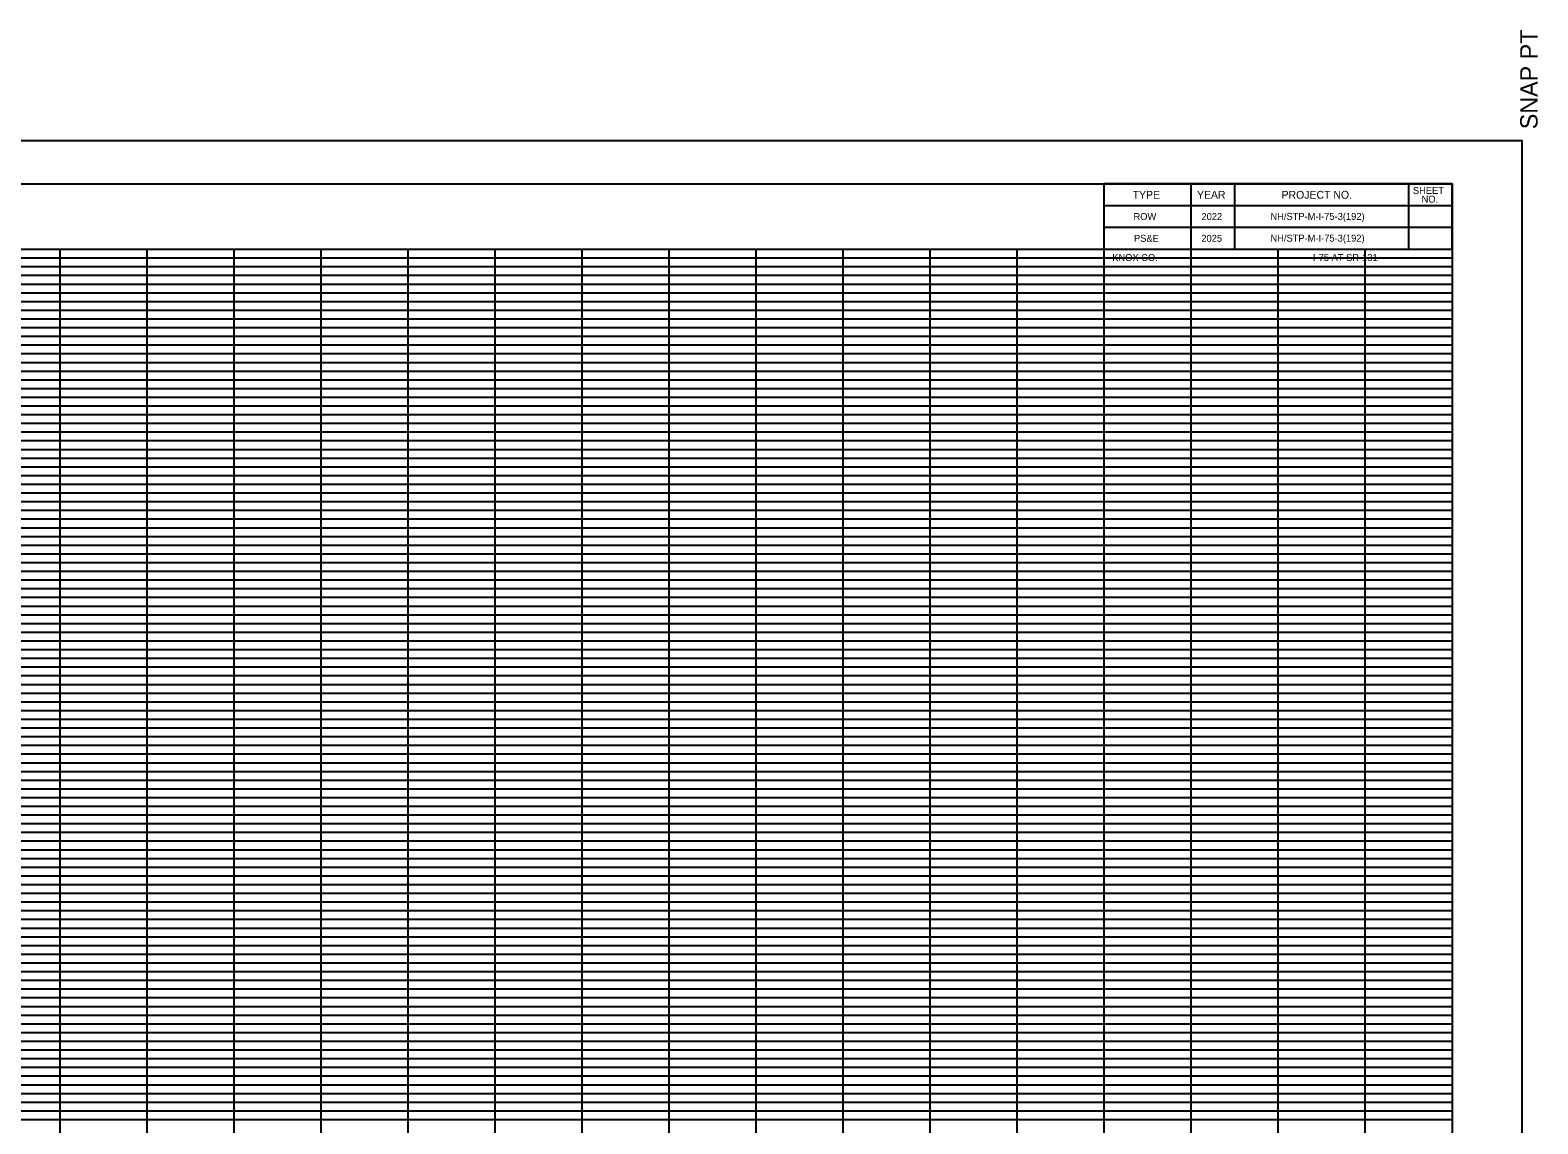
# Model space of a CAD drawing. Extents: x -1.4 to 33, y -2.5 to 22.5.
import ezdxf

# ---------------------------------------------------------------- set-up
doc = ezdxf.new("R2010")
doc.units = 0
for name, color, linetype in [('DESIGN - SCRATCH - User 1', 7, 'Continuous'), ('DESIGN - SHEET - Corner Text', 7, 'Continuous'), ('DESIGN - SHEET - Light Grid', 7, 'Continuous'), ('DESIGN - SHEET - Linework', 7, 'Continuous'), ('DESIGN - SHEET - Plot Shape', 7, 'Continuous')]:
    doc.layers.add(name, color=color, linetype=linetype)

msp = doc.modelspace()

# ---------------------------------------------------------------- linework, layer by layer
at = {"layer": 'DESIGN - SCRATCH - User 1'}
for p, q in [((28.5, 20.375), (28.5, 20.375)), ((29.25, 20.375), (29.25, 20.375)), ((30.5, 20.375), (30.5, 20.375)), ((31.75, 20.375), (31.75, 20.375)), ((28.5, 20.125), (28.5, 20.125)), ((29.25, 20.125), (29.25, 20.125)), ((30.5, 20.125), (30.5, 20.125)), ((31.75, 20.125), (31.75, 20.125))]:
    msp.add_line(p, q, dxfattribs=at)
at = {"layer": 'DESIGN - SHEET - Light Grid'}
for p, q in [((0, 19.9), (32, 19.9)), ((0, 19.8), (32, 19.8)), ((0, 19.7), (32, 19.7)), ((0, 19.6), (32, 19.6)), ((0, 19.5), (32, 19.5)), ((0, 19.4), (32, 19.4)), ((0, 19.3), (32, 19.3)), ((0, 19.2), (32, 19.2)), ((0, 19.1), (32, 19.1)), ((0, 18.9), (32, 18.9)), ((0, 18.8), (32, 18.8)), ((0, 18.7), (32, 18.7)), ((0, 18.6), (32, 18.6)), ((0, 18.5), (32, 18.5)), ((0, 18.4), (32, 18.4)), ((0, 18.3), (32, 18.3)), ((0, 18.2), (32, 18.2)), ((0, 18.1), (32, 18.1)), ((0, 17.9), (32, 17.9)), ((0, 17.8), (32, 17.8)), ((0, 17.7), (32, 17.7)), ((0, 17.6), (32, 17.6)), ((0, 17.5), (32, 17.5)), ((0, 17.4), (32, 17.4)), ((0, 17.3), (32, 17.3)), ((0, 17.2), (32, 17.2)), ((0, 17.1), (32, 17.1)), ((0, 16.9), (32, 16.9)), ((0, 16.8), (32, 16.8)), ((0, 16.7), (32, 16.7)), ((0, 16.6), (32, 16.6)), ((0, 16.5), (32, 16.5)), ((0, 16.4), (32, 16.4)), ((0, 16.3), (32, 16.3)), ((0, 16.2), (32, 16.2)), ((0, 16.1), (32, 16.1)), ((0, 15.9), (32, 15.9)), ((0, 15.8), (32, 15.8)), ((0, 15.7), (32, 15.7)), ((0, 15.6), (32, 15.6)), ((0, 15.5), (32, 15.5)), ((0, 15.4), (32, 15.4)), ((0, 15.3), (32, 15.3)), ((0, 15.2), (32, 15.2)), ((0, 15.1), (32, 15.1)), ((0, 14.9), (32, 14.9)), ((0, 14.8), (32, 14.8)), ((0, 14.7), (32, 14.7)), ((0, 14.6), (32, 14.6)), ((0, 14.5), (32, 14.5)), ((0, 14.4), (32, 14.4)), ((0, 14.3), (32, 14.3)), ((0, 14.2), (32, 14.2)), ((0, 14.1), (32, 14.1)), ((0, 13.9), (32, 13.9)), ((0, 13.8), (32, 13.8)), ((0, 13.7), (32, 13.7)), ((0, 13.6), (32, 13.6)), ((0, 13.5), (32, 13.5)), ((0, 13.4), (32, 13.4)), ((0, 13.3), (32, 13.3)), ((0, 13.2), (32, 13.2)), ((0, 13.1), (32, 13.1)), ((0, 12.9), (32, 12.9)), ((0, 12.8), (32, 12.8)), ((0, 12.7), (32, 12.7)), ((0, 12.6), (32, 12.6)), ((0, 12.5), (32, 12.5)), ((0, 12.4), (32, 12.4)), ((0, 12.3), (32, 12.3)), ((0, 12.2), (32, 12.2)), ((0, 12.1), (32, 12.1)), ((0, 11.9), (32, 11.9)), ((0, 11.8), (32, 11.8)), ((0, 11.7), (32, 11.7)), ((0, 11.6), (32, 11.6)), ((0, 11.5), (32, 11.5)), ((0, 11.4), (32, 11.4)), ((0, 11.3), (32, 11.3)), ((0, 11.2), (32, 11.2)), ((0, 11.1), (32, 11.1)), ((0, 10.9), (32, 10.9)), ((0, 10.8), (32, 10.8)), ((0, 10.7), (32, 10.7)), ((0, 10.6), (32, 10.6)), ((0, 10.5), (32, 10.5)), ((0, 10.4), (32, 10.4)), ((0, 10.3), (32, 10.3)), ((0, 10.2), (32, 10.2)), ((0, 10.1), (32, 10.1))]:
    msp.add_line(p, q, dxfattribs=at)
at = {"layer": 'DESIGN - SHEET - Linework'}
for p, q in [((32, 20.75), (28, 20.75)), ((28, 20), (28, 20.75)), ((29, 20), (29, 20.75)), ((29.5, 20), (29.5, 20.75)), ((31.5, 20), (31.5, 20.75)), ((32, 20), (32, 20.75)), ((32, 20.5), (28, 20.5)), ((32, 20.25), (28, 20.25)), ((0, 20), (32, 20)), ((16, 0), (16, 20)), ((17, 0), (17, 20)), ((18, 0), (18, 20)), ((19, 0), (19, 20)), ((20, 0), (20, 20)), ((21, 0), (21, 20)), ((22, 0), (22, 20)), ((23, 0), (23, 20)), ((24, 0), (24, 20)), ((25, 0), (25, 20)), ((26, 0), (26, 20)), ((27, 0), (27, 20)), ((28, 0), (28, 20)), ((29, 0), (29, 20)), ((30, 0), (30, 20)), ((31, 0), (31, 20)), ((0, 19), (32, 19)), ((0, 18), (32, 18)), ((0, 17), (32, 17)), ((0, 16), (32, 16)), ((0, 15), (32, 15)), ((0, 14), (32, 14)), ((0, 13), (32, 13)), ((0, 12), (32, 12)), ((0, 11), (32, 11)), ((0, 10), (32, 10))]:
    msp.add_line(p, q, dxfattribs=at)
msp.add_lwpolyline([(0, 20.75), (32, 20.75), (32, -0.25), (0, -0.25)], close=True, dxfattribs=at)
at = {"layer": 'DESIGN - SHEET - Plot Shape'}
msp.add_lwpolyline([(-1.2, 21.25), (32.8, 21.25), (32.8, -0.75), (-1.2, -0.75)], close=True, dxfattribs=at)

# ---------------------------------------------------------------- texts
at = {"layer": 'DESIGN - SHEET - Corner Text'}
msp.add_text('  SNAP PT', height=0.2, rotation=90, dxfattribs=at).set_placement((32.98, 21.23))
for s, p in [('  ROW  ', (28.277, 20.335)), ('2022', (29.117, 20.335)), ('NH/STP-M-I-75-3(192)', (29.91, 20.337)), ('PS&E', (28.342, 20.085)), ('2025', (29.116, 20.085)), ('NH/STP-M-I-75-3(192)', (29.91, 20.087)), ('KNOX CO.                                                            I-75 AT SR-131', (28.092, 19.864))]:
    msp.add_text(s, height=0.08, dxfattribs=at).set_placement(p)
at = {"layer": 'DESIGN - SHEET - Light Grid'}
for s, height, p in [('TYPE', 0.09, (28.326, 20.58)), ('YEAR', 0.09, (29.066, 20.58)), ('PROJECT NO.', 0.09, (30.038, 20.58)), ('SHEET', 0.08, (31.547, 20.635)), ('NO.', 0.08, (31.647, 20.535))]:
    msp.add_text(s, height=height, dxfattribs=at).set_placement(p)

doc.saveas('drawing.dxf')
